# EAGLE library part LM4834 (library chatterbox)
1.75W Audio Power Amplifier with DC Volume Control and Microphone Preamp
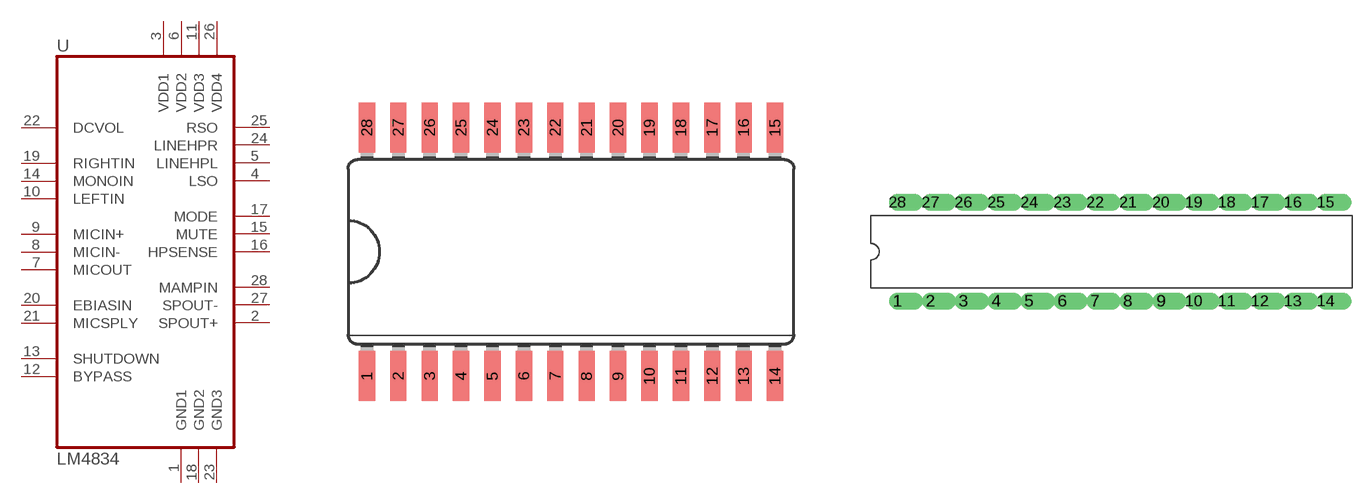
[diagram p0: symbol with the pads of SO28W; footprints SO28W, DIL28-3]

Designator prefix -

## LM4834MS  [SO28W]
1  GND1  pas
2  SPOUT+  out
3  VDD1  pas
4  LSO  out
5  LINEHPL  out
6  VDD2  pas
7  MICOUT  out
8  MICIN-  in
9  MICIN+  in
10  LEFTIN  in
11  VDD3  pas
12  BYPASS  in
13  SHUTDOWN  in
14  MONOIN  in
15  MUTE  in
16  HPSENSE  in
17  MODE  in
18  GND2  pas
19  RIGHTIN  in
20  EBIASIN  pas
21  MICSPLY  pas
22  DCVOL  in
23  GND3  pas
24  LINEHPR  out
25  RSO  out
26  VDD4  pas
27  SPOUT-  out
28  MAMPIN  in

## LM4834DI  [DIL28-3]
Pads as for SO28W

## Footprint SO28W (pad centres in mm)
SO28W Wide Small Outline package, 300 mil
smd 0.66 x 2.032: 1 -8.255,-5.029; 2 -6.985,-5.029; 3 -5.715,-5.029; 4 -4.445,-5.029; 5 -3.175,-5.029; 6 -1.905,-5.029; 7 -0.635,-5.029; 8 0.635,-5.029; 9 1.905,-5.029; 10 3.175,-5.029; 11 4.445,-5.029; 12 5.715,-5.029; 13 6.985,-5.029; 14 8.255,-5.029; 15 8.255,5.029; 16 6.985,5.029; 17 5.715,5.029; 18 4.445,5.029; 19 3.175,5.029; 20 1.905,5.029; 21 0.635,5.029; 22 -0.635,5.029; 23 -1.905,5.029; 24 -3.175,5.029; 25 -4.445,5.029; 26 -5.715,5.029; 27 -6.985,5.029; 28 -8.255,5.029

## Footprint DIL28-3 (pad centres in mm)
Dual In Line 28, 0.3 inch
drill 0.813 offset: 1 -16.51,-3.81; 2 -13.97,-3.81; 3 -11.43,-3.81; 4 -8.89,-3.81; 5 -6.35,-3.81; 6 -3.81,-3.81; 7 -1.27,-3.81; 8 1.27,-3.81; 9 3.81,-3.81; 10 6.35,-3.81; 11 8.89,-3.81; 12 11.43,-3.81; 13 13.97,-3.81; 14 16.51,-3.81; 15 16.51,3.81; 16 13.97,3.81; 17 11.43,3.81; 18 8.89,3.81; 19 6.35,3.81; 20 3.81,3.81; 21 1.27,3.81; 22 -1.27,3.81; 23 -3.81,3.81; 24 -6.35,3.81; 25 -8.89,3.81; 26 -11.43,3.81; 27 -13.97,3.81; 28 -16.51,3.81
